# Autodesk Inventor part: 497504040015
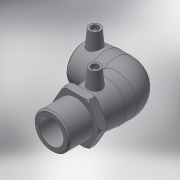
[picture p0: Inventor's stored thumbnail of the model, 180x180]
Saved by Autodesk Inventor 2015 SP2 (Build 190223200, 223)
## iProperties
Created: 2017-06
Part Number: 497504040015
Material: Generic
Description: PE Male Transition Elbow 90° 40x 1 1_2
Document SubType Name: Modeling
Designer: KIM
Mass: 258.065 g
Surface Area: 588.849 cm^2
Volume: 258.065 cm^3
Density: 1 g/cm^3
Appearance: Default
Author: KIM
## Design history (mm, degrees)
derived "497504.ipt"
feature "Solid1::497504.ipt"
feature "Solid2::497504.ipt"
tag "TaggingFeature1"
workplane "Work Plane2"
body "Solid1"
body "Solid2"
other parameters: "d2" = 55, "d4" = 29.33333, "d5" = 49.5, "d8" = 168 deg, "d10" = 17.6, "d11" = 5.86667, "d29" = 47, "d30" = 15, "d31" = 45.76, "d34" = 5 deg, "d41" = 4, "d42" = 14, "d43" = 0, "d48" = 60.5, "d50" = 4, "d51" = 17.6, "d52" = 44, "d54" = 90 deg, "d86" = 3, "d87" = 0, "d93" = 0.1, "d94" = 11, "d95" = 47.803, "d96" = 33.4621, "d98" = 44, "d99" = 66, "d100" = 39.6, "d102" = 2, "d106" = 0, "d108" = 39.6, "d114" = 44, "d115" = 0, "d116" = -44, "L_" = 132, "L_1" = 44, "A_" = 47, "d_2" = 12, "L_2" = 44, "D_1" = 55, "R_" = 47.803
